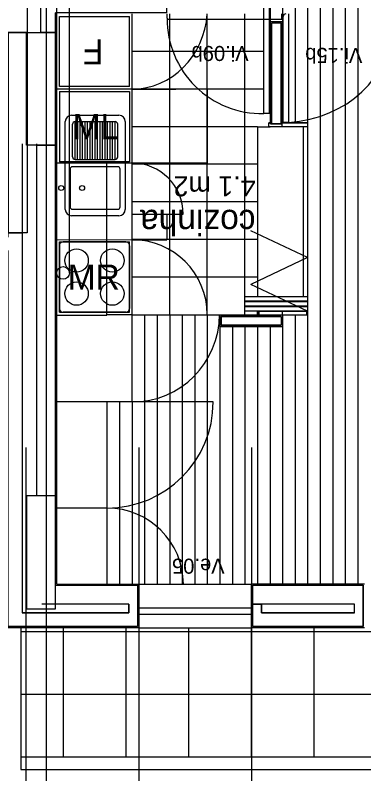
# Model space of a CAD drawing. Extents: x 1248 to 1356, y -443 to -224.
# Drawn here: x 1318.31 to 1321.09, y -248.09 to -242.03 of the extents above; entities that cross this region are included whole.
import ezdxf

# ---------------------------------------------------------------- set-up
doc = ezdxf.new("R2010")
doc.units = 0
for name, color, linetype in [('corte', 7, 'Continuous'), ('estereoctomias', 7, 'Continuous'), ('estrutura-eixos', 7, 'Continuous'), ('Level 1', 7, 'Continuous'), ('Level 10', 7, 'Continuous'), ('Level 11', 7, 'Continuous'), ('Level 13', 7, 'Continuous'), ('Level 2', 7, 'Continuous'), ('Level 3', 7, 'Continuous'), ('Level 4', 7, 'Continuous'), ('Level 40', 7, 'Continuous'), ('Level 60', 7, 'Continuous'), ('mob-fixo', 7, 'Continuous'), ('revestimentos', 7, 'Continuous'), ('vermelhos-cont', 7, 'Continuous'), ('vermelhos-tracej', 7, 'Continuous')]:
    doc.layers.add(name, color=color, linetype=linetype)

msp = doc.modelspace()

# ---------------------------------------------------------------- linework, layer by layer
at = {"layer": 'corte'}
for p, q in [((1318.5144, -242.1713), (1318.5144, -240.304)), ((1320.346, -242.892), (1320.346, -242.902)), ((1320.436, -242.892), (1320.436, -242.924)), ((1318.481, -245.8713), (1318.481, -243.0613)), ((1319.214, -246.734), (1318.521, -246.734)), ((1321.014, -246.734), (1320.274, -246.734)), ((1319.214, -246.804), (1318.3633, -246.804)), ((1321.014, -246.804), (1320.274, -246.804)), ((1319.284, -246.914), (1318.2537, -246.914)), ((1321.084, -246.914), (1320.204, -246.914))]:
    msp.add_line(p, q, dxfattribs=at)
for points in [[(1318.4044, -242.1713), (1318.2044, -242.1713), (1318.2044, -241.4713), (1318.4044, -241.4713)], [(1318.4044, -243.7713), (1318.2544, -243.7713), (1318.2544, -242.1713), (1318.4044, -242.1713)], [(1318.6303, -243.0713), (1318.4003, -243.0713), (1318.4003, -242.1713), (1318.6303, -242.1713)], [(1318.6303, -245.8713), (1318.4003, -245.8713), (1318.4003, -246.7713), (1318.6303, -246.7713)]]:
    msp.add_lwpolyline(points, close=True, dxfattribs=at)
at = {"layer": 'estereoctomias'}
for points in [[(1319.516, -241.944), (1319.516, -242.014), (1318.631, -242.014), (1318.631, -242.1713), (1318.5144, -242.1713), (1318.5144, -241.944), (1319.5075, -241.944)], [(1320.426, -242.094), (1320.426, -242.902), (1320.356, -242.902), (1320.356, -242.094)], [(1320.436, -242.892), (1320.641, -242.892), (1320.641, -242.924), (1320.331, -242.924), (1320.331, -242.892), (1320.346, -242.892), (1320.346, -242.902), (1320.436, -242.902)], [(1318.6303, -245.8713), (1318.481, -245.8713), (1318.481, -243.0713), (1318.6303, -243.0713)], [(1315.3634, -243.584), (1315.3634, -243.734), (1313.7273, -243.734), (1313.7273, -243.804), (1318.2537, -243.804), (1318.2537, -243.7713), (1318.3641, -243.7712), (1318.3633, -246.804), (1319.214, -246.804), (1319.214, -246.734), (1318.6303, -246.734), (1318.631, -246.584), (1319.284, -246.584), (1319.284, -246.914), (1318.2537, -246.914), (1318.2537, -243.914), (1313.6573, -243.914), (1313.6573, -243.584)], [(1320.431, -244.4379), (1320.431, -244.5079), (1319.951, -244.5079), (1319.951, -244.4379)], [(1320.641, -244.3959), (1320.641, -244.4279), (1320.241, -244.4279), (1320.241, -244.3959)], [(1321.084, -246.584), (1321.084, -246.914), (1320.204, -246.914), (1320.204, -246.734), (1320.274, -246.734), (1320.274, -246.804), (1321.014, -246.804), (1321.014, -246.734), (1320.204, -246.734), (1320.204, -246.584)]]:
    msp.add_lwpolyline(points, close=True, dxfattribs=at)
at = {"layer": 'estrutura-eixos'}
msp.add_line((1318.3533, -246.924), (1318.3533, -248.054), dxfattribs=at)
at = {"layer": 'Level 1'}
for p, q in [((1318.631, -246.584), (1318.631, -242.014)), ((1320.356, -242.902), (1320.356, -242.094)), ((1320.356, -242.094), (1320.426, -242.094)), ((1320.426, -242.094), (1320.426, -242.902)), ((1320.346, -242.892), (1320.331, -242.892)), ((1320.331, -242.924), (1320.331, -242.892)), ((1320.641, -242.924), (1320.331, -242.924)), ((1320.346, -242.902), (1320.436, -242.902)), ((1320.641, -242.892), (1320.436, -242.892)), ((1320.641, -242.892), (1320.641, -242.924)), ((1318.3633, -243.0613), (1318.3633, -246.804)), ((1320.431, -244.4379), (1319.951, -244.4379)), ((1319.951, -244.4379), (1319.951, -244.5079)), ((1320.241, -244.3959), (1320.241, -244.424)), ((1320.641, -244.3959), (1320.241, -244.3959)), ((1320.241, -244.3959), (1320.241, -244.4279)), ((1320.251, -244.3959), (1320.251, -244.4279)), ((1320.431, -244.4379), (1320.431, -244.5079)), ((1320.441, -244.4279), (1320.441, -244.3959)), ((1320.641, -244.4279), (1320.441, -244.4279)), ((1320.631, -244.3959), (1320.631, -244.4279)), ((1320.641, -244.3959), (1320.641, -244.4279)), ((1319.951, -244.5079), (1320.431, -244.5079)), ((1318.631, -246.584), (1319.284, -246.584)), ((1319.284, -246.584), (1319.284, -246.914)), ((1321.084, -246.584), (1320.204, -246.584)), ((1320.204, -246.914), (1320.204, -246.584)), ((1321.084, -246.914), (1321.084, -246.584)), ((1319.214, -246.734), (1319.214, -246.804)), ((1320.274, -246.804), (1320.274, -246.734)), ((1321.014, -246.804), (1321.014, -246.734))]:
    msp.add_line(p, q, dxfattribs=at)
at = {"layer": 'Level 10'}
for p, q in [((1320.341, -240.424), (1320.341, -242.892)), ((1320.441, -240.424), (1320.441, -242.892)), ((1320.541, -240.439), (1320.541, -242.892)), ((1320.641, -240.439), (1320.641, -242.892)), ((1320.741, -240.439), (1320.741, -246.574)), ((1320.841, -240.439), (1320.841, -246.574)), ((1320.941, -240.439), (1320.941, -246.574)), ((1321.041, -240.439), (1321.041, -246.574)), ((1319.541, -244.428), (1319.541, -242.024)), ((1319.841, -244.428), (1319.841, -242.024)), ((1320.141, -244.428), (1320.141, -242.024)), ((1320.291, -242.324), (1319.241, -242.324)), ((1320.291, -242.624), (1319.241, -242.624)), ((1320.291, -242.624), (1319.241, -242.624)), ((1320.241, -242.924), (1319.241, -242.924)), ((1320.241, -243.224), (1319.241, -243.224)), ((1320.241, -243.224), (1319.241, -243.224)), ((1320.241, -243.524), (1319.241, -243.524)), ((1320.241, -243.824), (1319.241, -243.824)), ((1320.241, -244.124), (1319.241, -244.124)), ((1319.941, -244.428), (1319.241, -244.428)), ((1319.341, -244.428), (1319.341, -246.574)), ((1319.441, -244.428), (1319.441, -246.574)), ((1319.541, -244.428), (1319.541, -246.574)), ((1319.641, -244.428), (1319.641, -246.574)), ((1319.741, -244.428), (1319.741, -246.574)), ((1319.841, -244.428), (1319.841, -246.574)), ((1320.541, -244.4279), (1320.541, -246.574)), ((1320.641, -244.4279), (1320.641, -246.574)), ((1319.941, -244.5179), (1319.941, -246.574)), ((1320.041, -244.5179), (1320.041, -246.574)), ((1320.141, -244.5179), (1320.141, -246.574)), ((1320.241, -244.5179), (1320.241, -246.574)), ((1320.341, -244.5179), (1320.341, -246.574)), ((1320.441, -244.5179), (1320.441, -246.574)), ((1319.141, -245.121), (1319.141, -246.574)), ((1319.241, -245.121), (1319.241, -246.574)), ((1318.3533, -246.954), (1323.8933, -246.954)), ((1318.6933, -247.954), (1318.6933, -246.924)), ((1319.1933, -247.954), (1319.1933, -246.924)), ((1319.6933, -247.954), (1319.6933, -246.924)), ((1320.1933, -247.954), (1320.1933, -246.924)), ((1320.6933, -247.954), (1320.6933, -246.924)), ((1318.3533, -247.454), (1323.8933, -247.454)), ((1318.3533, -247.954), (1323.8933, -247.954))]:
    msp.add_line(p, q, dxfattribs=at)
at = {"layer": 'Level 11'}
for p, q in [((1318.661, -242.604), (1318.661, -242.044)), ((1318.661, -242.044), (1319.221, -242.044)), ((1319.221, -242.604), (1319.221, -242.044)), ((1319.221, -242.604), (1318.661, -242.604)), ((1318.7661, -243.1651), (1318.7661, -242.9035)), ((1318.7861, -242.8835), (1319.1061, -242.8835)), ((1318.7861, -243.1851), (1318.7861, -242.8835)), ((1318.8061, -243.1851), (1318.8061, -242.8835)), ((1318.8261, -243.1851), (1318.8261, -242.8835)), ((1318.8461, -243.1851), (1318.8461, -242.8835)), ((1318.8661, -243.1851), (1318.8661, -242.8835)), ((1318.8861, -243.1851), (1318.8861, -242.8835)), ((1318.9061, -243.1851), (1318.9061, -242.8835)), ((1318.9261, -243.1851), (1318.9261, -242.8835)), ((1318.9461, -243.1851), (1318.9461, -242.8835)), ((1318.9661, -243.1851), (1318.9661, -242.8835)), ((1318.9861, -243.1851), (1318.9861, -242.8835)), ((1319.0061, -243.1851), (1319.0061, -242.8835)), ((1319.0261, -243.1851), (1319.0261, -242.8835)), ((1319.0461, -243.1851), (1319.0461, -242.8835)), ((1319.0661, -243.1851), (1319.0661, -242.8835)), ((1319.0861, -243.1851), (1319.0861, -242.8835)), ((1319.1061, -243.1851), (1319.1061, -242.8835)), ((1319.1261, -243.1651), (1319.1261, -242.9035)), ((1318.7861, -243.1851), (1319.1061, -243.1851)), ((1318.7461, -243.2635), (1318.7461, -243.5635)), ((1319.1261, -243.2435), (1318.7661, -243.2435)), ((1319.1461, -243.5635), (1319.1461, -243.2635)), ((1318.7661, -243.5835), (1319.1261, -243.5835)), ((1318.6611, -243.874), (1318.6611, -244.374)), ((1319.1911, -243.844), (1318.6911, -243.844)), ((1319.2211, -243.874), (1319.2211, -244.374)), ((1319.1911, -244.404), (1318.6911, -244.404))]:
    msp.add_line(p, q, dxfattribs=at)
for points in [[(1318.7583, -242.8333), (1319.1367, -242.8333)], [(1318.7083, -243.5847), (1318.7083, -242.8833)], [(1319.1867, -242.8833), (1319.1867, -243.5847)], [(1319.1367, -243.6347), (1318.7583, -243.6347)]]:
    msp.add_lwpolyline(points, dxfattribs=at)
for centre, radius in [((1318.6762, -243.4135), 0.0199), ((1318.8421, -243.4135), 0.0199), ((1318.7985, -243.9919), 0.0936), ((1319.0837, -243.9919), 0.0936), ((1318.7985, -244.2561), 0.0936), ((1319.0837, -244.2561), 0.0936)]:
    msp.add_circle(centre, radius, dxfattribs=at)
for centre, radius, start, end in [((1318.7583, -242.8833), 0.05, 90, 180), ((1319.1367, -242.8833), 0.05, 0, 90), ((1318.7861, -242.9035), 0.02, 90, 180), ((1319.1061, -242.9035), 0.02, 0, 90), ((1318.7861, -243.1651), 0.02, 180, 270), ((1319.1061, -243.1651), 0.02, 270, 0), ((1318.7661, -243.2635), 0.02, 90, 180), ((1319.1261, -243.2635), 0.02, 0, 90), ((1318.7583, -243.5847), 0.05, 180, 270), ((1318.7661, -243.5635), 0.02, 180, 270), ((1319.1261, -243.5635), 0.02, 270, 0), ((1319.1367, -243.5847), 0.05, 270, 0), ((1318.6911, -243.874), 0.03, 89.99985, 180.0002), ((1319.1911, -243.874), 0.03, 0.00009, 90.0001), ((1318.6911, -244.374), 0.03, 180.00021, 269.99999), ((1319.1911, -244.374), 0.03, 270.00005, 0.00002)]:
    msp.add_arc(centre, radius, start, end, dxfattribs=at)
at = {"layer": 'Level 13'}
for p, q in [((1320.291, -242.819), (1320.291, -241.924)), ((1320.336, -242.819), (1320.336, -241.924)), ((1320.336, -242.819), (1320.336, -241.924)), ((1320.336, -242.819), (1320.336, -241.924)), ((1319.241, -245.121), (1319.241, -242.024)), ((1320.446, -242.8898), (1320.446, -242.044)), ((1320.491, -242.8898), (1320.491, -242.024)), ((1319.241, -242.624), (1318.641, -242.624)), ((1320.336, -242.819), (1320.291, -242.819)), ((1320.491, -242.8898), (1320.446, -242.8898)), ((1320.641, -244.2809), (1320.141, -244.2809)), ((1320.141, -244.3159), (1320.141, -244.2809)), ((1320.641, -244.3159), (1320.141, -244.3159)), ((1320.641, -244.3209), (1320.141, -244.3209)), ((1320.141, -244.3559), (1320.141, -244.3209)), ((1320.641, -244.3559), (1320.141, -244.3559)), ((1320.641, -244.3609), (1320.141, -244.3609)), ((1320.141, -244.3959), (1320.141, -244.3609)), ((1320.241, -244.3959), (1320.141, -244.3959)), ((1319.241, -245.121), (1318.641, -245.121)), ((1319.041, -245.121), (1319.041, -246.574))]:
    msp.add_line(p, q, dxfattribs=at)
msp.add_arc((1320.466, -242.044), 0.02, 90, 180, dxfattribs=at)
at = {"layer": 'Level 2'}
for p, q in [((1320.241, -242.924), (1320.241, -244.2809)), ((1320.241, -242.924), (1320.341, -242.924)), ((1320.641, -242.924), (1320.641, -244.3959)), ((1320.241, -244.3159), (1320.241, -244.3209)), ((1320.241, -244.3559), (1320.241, -244.3609)), ((1319.294, -246.574), (1320.194, -246.574)), ((1319.294, -246.764), (1320.194, -246.764)), ((1319.294, -246.814), (1320.194, -246.814)), ((1319.294, -246.924), (1320.194, -246.924)), ((1318.3533, -248.054), (1323.8933, -248.054))]:
    msp.add_line(p, q, dxfattribs=at)
at = {"layer": 'Level 3'}
for p, q in [((1319.241, -243.214), (1318.641, -243.214)), ((1319.041, -244.424), (1319.041, -243.214)), ((1319.041, -244.424), (1319.241, -244.424)), ((1319.041, -245.968), (1318.641, -245.968))]:
    msp.add_line(p, q, dxfattribs=at)
at = {"layer": 'Level 4'}
for p, q in [((1319.521, -242.059), (1319.521, -242.024)), ((1320.436, -242.069), (1319.521, -242.069)), ((1320.436, -242.069), (1320.436, -242.024)), ((1318.661, -242.644), (1318.661, -243.204)), ((1318.661, -242.644), (1319.221, -242.644)), ((1319.221, -242.644), (1319.221, -243.204)), ((1319.241, -242.624), (1319.591, -242.624)), ((1319.241, -242.624), (1319.591, -242.624)), ((1319.841, -242.624), (1319.841, -243.214)), ((1320.606, -242.924), (1320.606, -244.2809)), ((1319.221, -243.204), (1318.661, -243.204)), ((1319.841, -243.214), (1319.241, -243.214)), ((1319.241, -243.622), (1319.649, -243.622)), ((1319.5185, -243.622), (1319.5185, -243.8263)), ((1320.641, -243.9691), (1320.1888, -243.7557)), ((1318.641, -243.824), (1319.241, -243.8263)), ((1319.241, -243.8263), (1319.5185, -243.8263)), ((1318.661, -243.844), (1319.221, -243.844)), ((1318.661, -244.404), (1318.661, -243.844)), ((1319.221, -244.404), (1319.221, -243.844)), ((1320.641, -243.9691), (1320.1888, -244.1825)), ((1320.641, -244.3959), (1320.1888, -244.1825)), ((1318.641, -244.428), (1319.041, -244.428)), ((1318.661, -244.404), (1319.221, -244.404)), ((1319.888, -245.121), (1319.041, -245.121))]:
    msp.add_line(p, q, dxfattribs=at)
for centre, radius, start, end in [((1320.2752, -242.0652), 0.7542, 179.52968, 271.19857), ((1319.241, -243.622), 0.408, 0, 90), ((1319.241, -244.4263), 0.6, 0.2225, 90), ((1319.241, -244.424), 0.697, 270, 0), ((1319.041, -245.121), 0.847, 270, 0)]:
    msp.add_arc(centre, radius, start, end, dxfattribs=at)
for centre, major_axis, ratio, start_param, end_param in [((1319.241, -241.9731), (0, -0.6509), 0.924693, 0, 1.492592), ((1320.4256, -242.124), (-0.8834, 0), 0.869287, 1.644887, 3.141577), ((1319.041, -246.574), (0.609, 0), 0.995061, 0, 1.570796)]:
    msp.add_ellipse(centre, major_axis=major_axis, ratio=ratio, start_param=start_param, end_param=end_param, dxfattribs=at)
at = {"layer": 'mob-fixo'}
for p, q in [((1318.641, -244.091), (1318.641, -240.604)), ((1318.741, -244.091), (1318.741, -240.604))]:
    msp.add_line(p, q, dxfattribs=at)
msp.add_circle((1318.691, -244.091), 0.05, dxfattribs=at)
at = {"layer": 'revestimentos'}
for p, q in [((1318.641, -246.574), (1318.641, -242.024)), ((1320.346, -242.902), (1320.346, -242.084)), ((1320.346, -242.084), (1320.436, -242.084)), ((1320.436, -242.084), (1320.436, -242.892)), ((1320.441, -244.4279), (1319.941, -244.4279)), ((1319.941, -244.4279), (1319.941, -244.5179)), ((1320.441, -244.4279), (1320.441, -244.5179)), ((1319.941, -244.5179), (1320.441, -244.5179)), ((1318.641, -246.574), (1319.294, -246.574)), ((1319.294, -246.574), (1319.294, -246.924)), ((1320.194, -246.924), (1320.194, -246.574)), ((1321.094, -246.574), (1320.194, -246.574)), ((1319.294, -246.924), (1318.2437, -246.924)), ((1321.094, -246.924), (1320.194, -246.924))]:
    msp.add_line(p, q, dxfattribs=at)
at = {"layer": 'vermelhos-cont'}
msp.add_line((1318.5594, -250.7923), (1318.5594, -229.6198), dxfattribs=at)
at = {"layer": 'vermelhos-tracej'}
for p, q in [((1318.394, -245.4838), (1318.394, -250.4459)), ((1319.294, -245.4838), (1319.294, -250.4459)), ((1320.194, -245.4838), (1320.194, -250.4459))]:
    msp.add_line(p, q, dxfattribs=at)

# ---------------------------------------------------------------- texts
at = {"layer": 'Level 11'}
msp.add_text('F', height=0.2, rotation=180, dxfattribs=at).set_placement((1319.0125, -242.2263))
for s, p in [('ML', (1318.7671, -243.024)), ('MR', (1318.7273, -244.224))]:
    msp.add_text(s, height=0.2, dxfattribs=at).set_placement(p)
at = {"layer": 'Level 40'}
for s, p in [('Vi.09b', (1320.1705, -242.2797)), ('Vi.15b', (1321.0771, -242.295)), ('Ve.05', (1319.979, -246.3717))]:
    msp.add_text(s, height=0.12, rotation=180.00001, dxfattribs=at).set_placement(p)
at = {"layer": 'Level 60'}
for s, height, p in [('4.1 m2', 0.16, (1320.2259, -243.3196)), ('cozinha', 0.2, (1320.2259, -243.5874))]:
    msp.add_text(s, height=height, rotation=180, dxfattribs=at).set_placement(p)

doc.saveas('drawing.dxf')
